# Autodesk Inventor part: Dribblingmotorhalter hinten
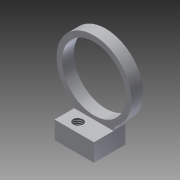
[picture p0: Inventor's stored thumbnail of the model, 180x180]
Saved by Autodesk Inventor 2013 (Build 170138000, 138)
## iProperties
Created: 2012-07
Part Number: Dribblingmotorhalter hinten
Material: Aluminium 6061
Document SubType Name: Modeling
Designer: rYan
Density: 2.71 g/cm^3
Mass: 1.28692 g
Surface Area: 7.17418 cm^2
Volume: 0.474878 cm^3
Author: rYan
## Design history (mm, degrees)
sketch "Skizze1"
  geometry: L1 (0, -4.6)-(0, 27.6) reference; L2 (-8.139, 23)-(7.861, 23); L3 (-9.5, 13.5)-(9.5, 13.5); L4 (-5, 4.5)-(-5, 0); L5 (-5, 0)-(5, 0); L6 (5, 0)-(5, 4.5); L7 (-14.556, 0)-(14.556, 0) reference; A1 r 9.5 centre (0, 13.5) between (9.5, 13.5) and (-9.5, 13.5); A2 r 9.5 centre (0, 13.5) between (-9.5, 13.5) and (-5.7, 5.9); A3 r 9.5 centre (0, 13.5) between (5.7, 5.9) and (9.5, 13.5); A4 r 1.75 centre (-6.75, 4.5) between (-5, 4.5) and (-5.7, 5.9); A5 r 1.75 centre (6.75, 4.5) between (5.7, 5.9) and (5, 4.5); 1 further point
  constraints: 10 end point, 10 point on circle, 6 tangent, 5 centre point, 2 parallel, 2 perpendicular, 1 collinear, 1 midpoint, 1 symmetric about line, 3 other
  dimensions: "d43" = 9.5 radius of A1; "d48" = 10 distance of L4.end L5.end; "d96" = 9.5 radius of A3 (= d43); "d97" = 13.5 distance between parallel lines of L7 L3; "d98" = 4.5 distance of L4.start L4.end
extrude "Extrusion1" new body sketch "Skizze1" distance "d3" = 3; taper "d4" = 0 deg
sketch "Skizze2"
  geometry: L1 (0, 27.6)-(0, -4.6) reference; L2 (-5, 0)-(-5, 4.5) reference; L3 (5, 0)-(-5, 0) reference; L4 (5, 4.5)-(5, 0) reference; L5 (-5, 4.5)-(5, 4.5); L6 (5, 4.5)-(5, 0); L7 (5, 0)-(-5, 0); L8 (-5, 0)-(-5, 4.5); 1 further point
  constraints: 8 end point, 2 parallel, 1 horizontal, 1 perpendicular
extrude "Extrusion2" join sketch "Skizze2" distance "d7" = 5; taper "d8" = 0 deg
sketch "Skizze3"
  geometry: L1 (0, 21.5)-(0, 0); 6 further points
  constraints: 2 end point, 1 coincident, 1 point on line, 1 other
hole "Bohrung1" sketch "Skizze3" diameter "d10" = 16.2; stored, may be unused: countersink angle "d14" = 90 deg, drill point angle "d16" = 118 deg; dims "d11" = 6, "d12" = 9, "d13" = 1, "d15" = 8
sketch "Skizze10"
  geometry: L1 (10, -8)-(10, 0) reference; L2 (0, 0)-(10, 0) reference; L3 (0, -8)-(0, 0) reference; L4 (10, -8)-(0, -8) reference; 2 further points
  dimensions: "d78" = 3.5 distance from line of L1 point (6.5, -5.5); "d99" = 2.5 distance from line of L4 point (6.5, -5.5)
hole "Bohrung6" sketch "Skizze10" at (6.5, -5.5) diameter "d79" = 2.459; stored, may be unused: countersink angle "d83" = 90 deg, drill point angle "d85" = 118 deg; dims "d80" = 3, "d81" = 4, "d82" = 2, "d84" = 4
sketch "Skizze11"
  geometry: L1 (10, -8)-(10, 0) reference; L2 (0, 0)-(10, 0) reference; L3 (0, -8)-(0, 0) reference; L4 (10, -8)-(0, -8) reference; L5 (0, -4)-(10, -4); L6 (1.8, -2)-(1.8, -6); C1 r 1.23 at (6.5, -5.5) reference; 1 further point
  constraints: 4 end point, 2 midpoint, 1 perpendicular, 1 symmetric about line
  dimensions: "d86" = 4 distance of L6.start L6.end; "d88" = 1.8 distance between parallel lines of L6 L3
hole "Bohrung7" sketch "Skizze11" at (1.8, -2), (1.8, -6) diameter "d89" = 2; stored, may be unused: countersink angle "d93" = 90 deg, drill point angle "d95" = 118 deg; dims "d90" = 6, "d91" = 4, "d92" = 2, "d94" = 3
node "Volumenkörper1"
node "Projizierte Kontur1"
node "Projizierte Kontur2"
